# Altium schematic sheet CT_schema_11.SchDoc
size 632 x 434 mm
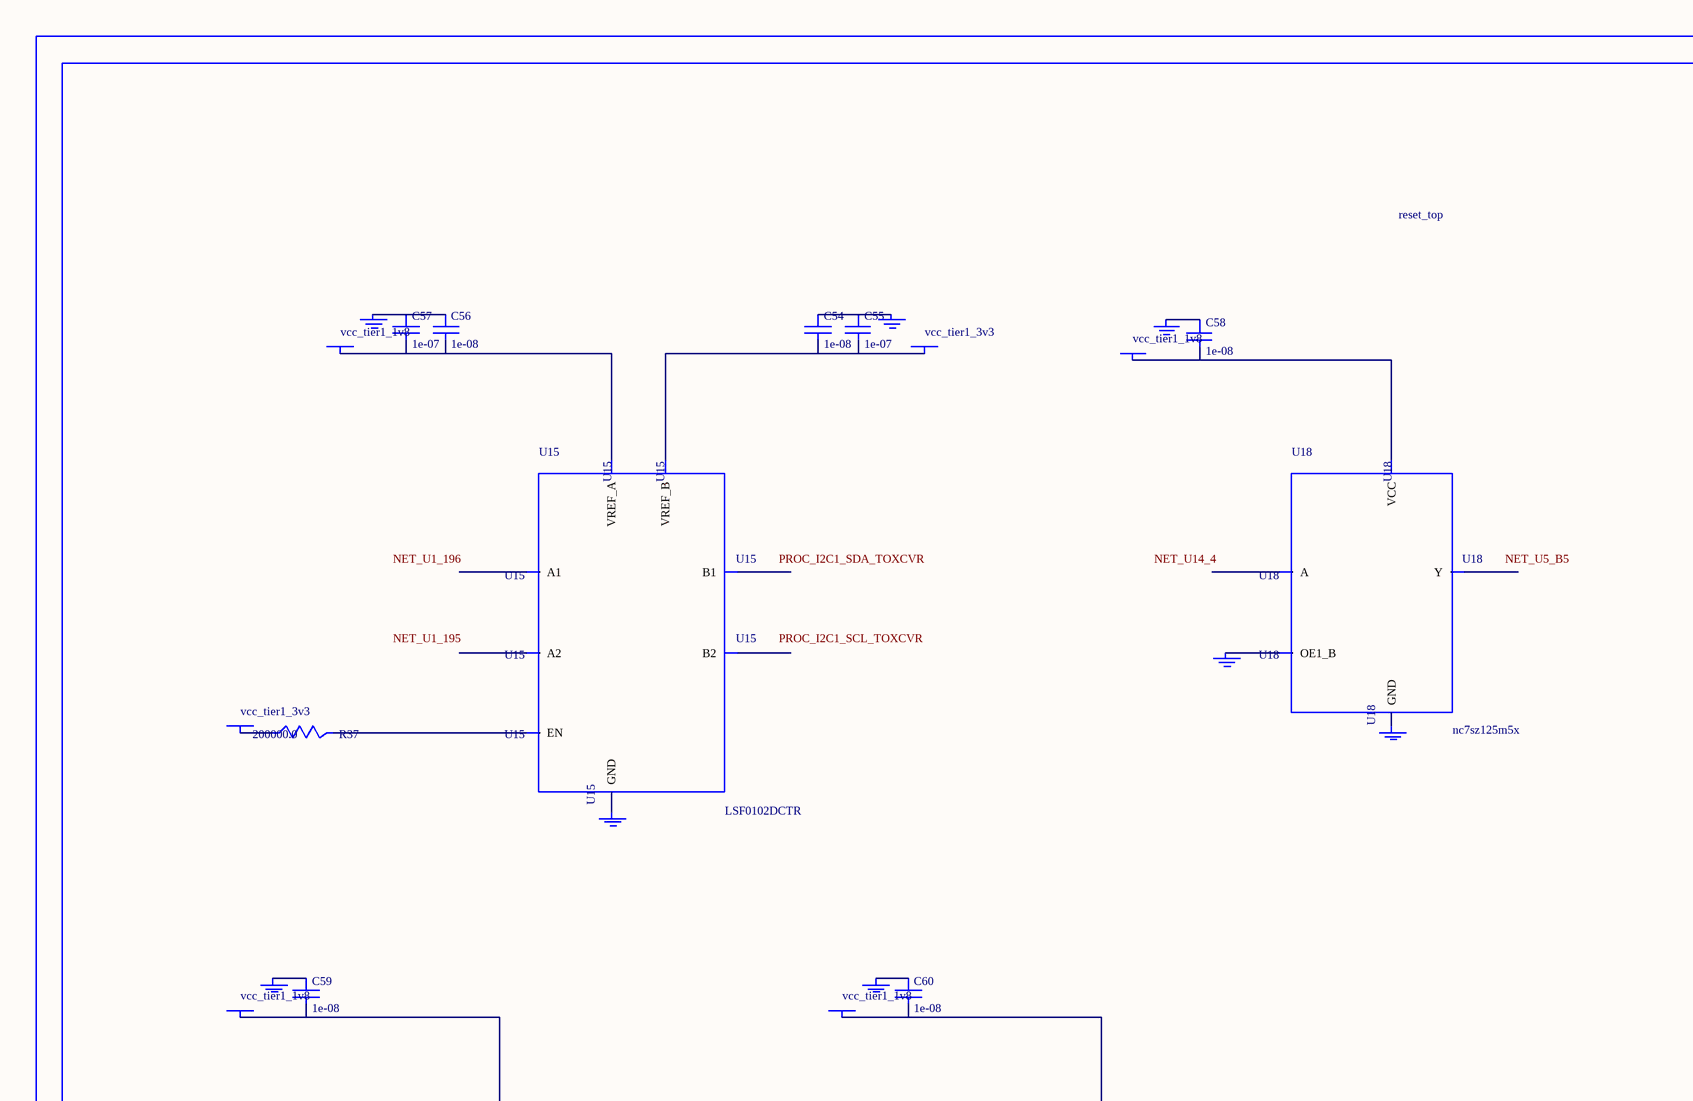
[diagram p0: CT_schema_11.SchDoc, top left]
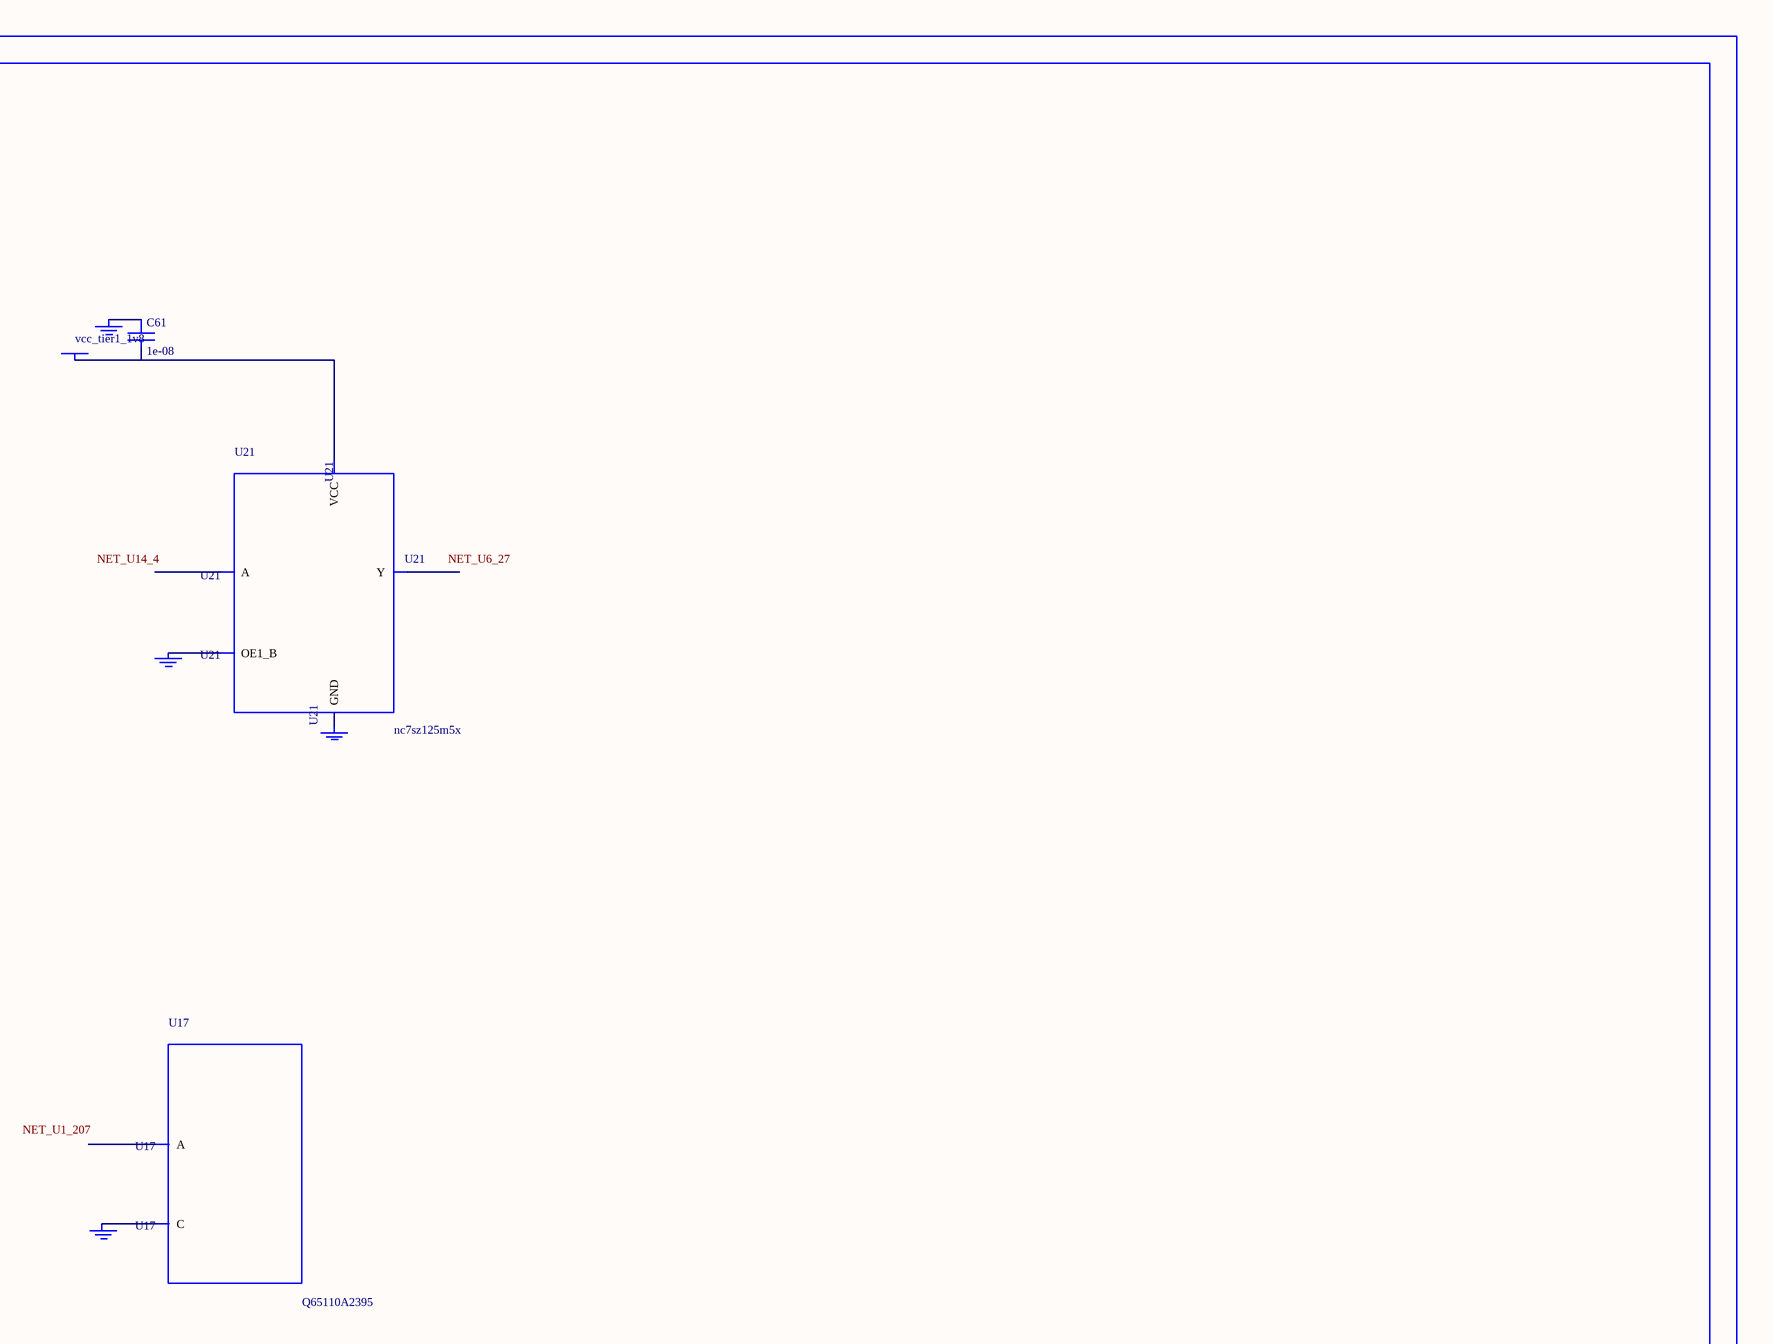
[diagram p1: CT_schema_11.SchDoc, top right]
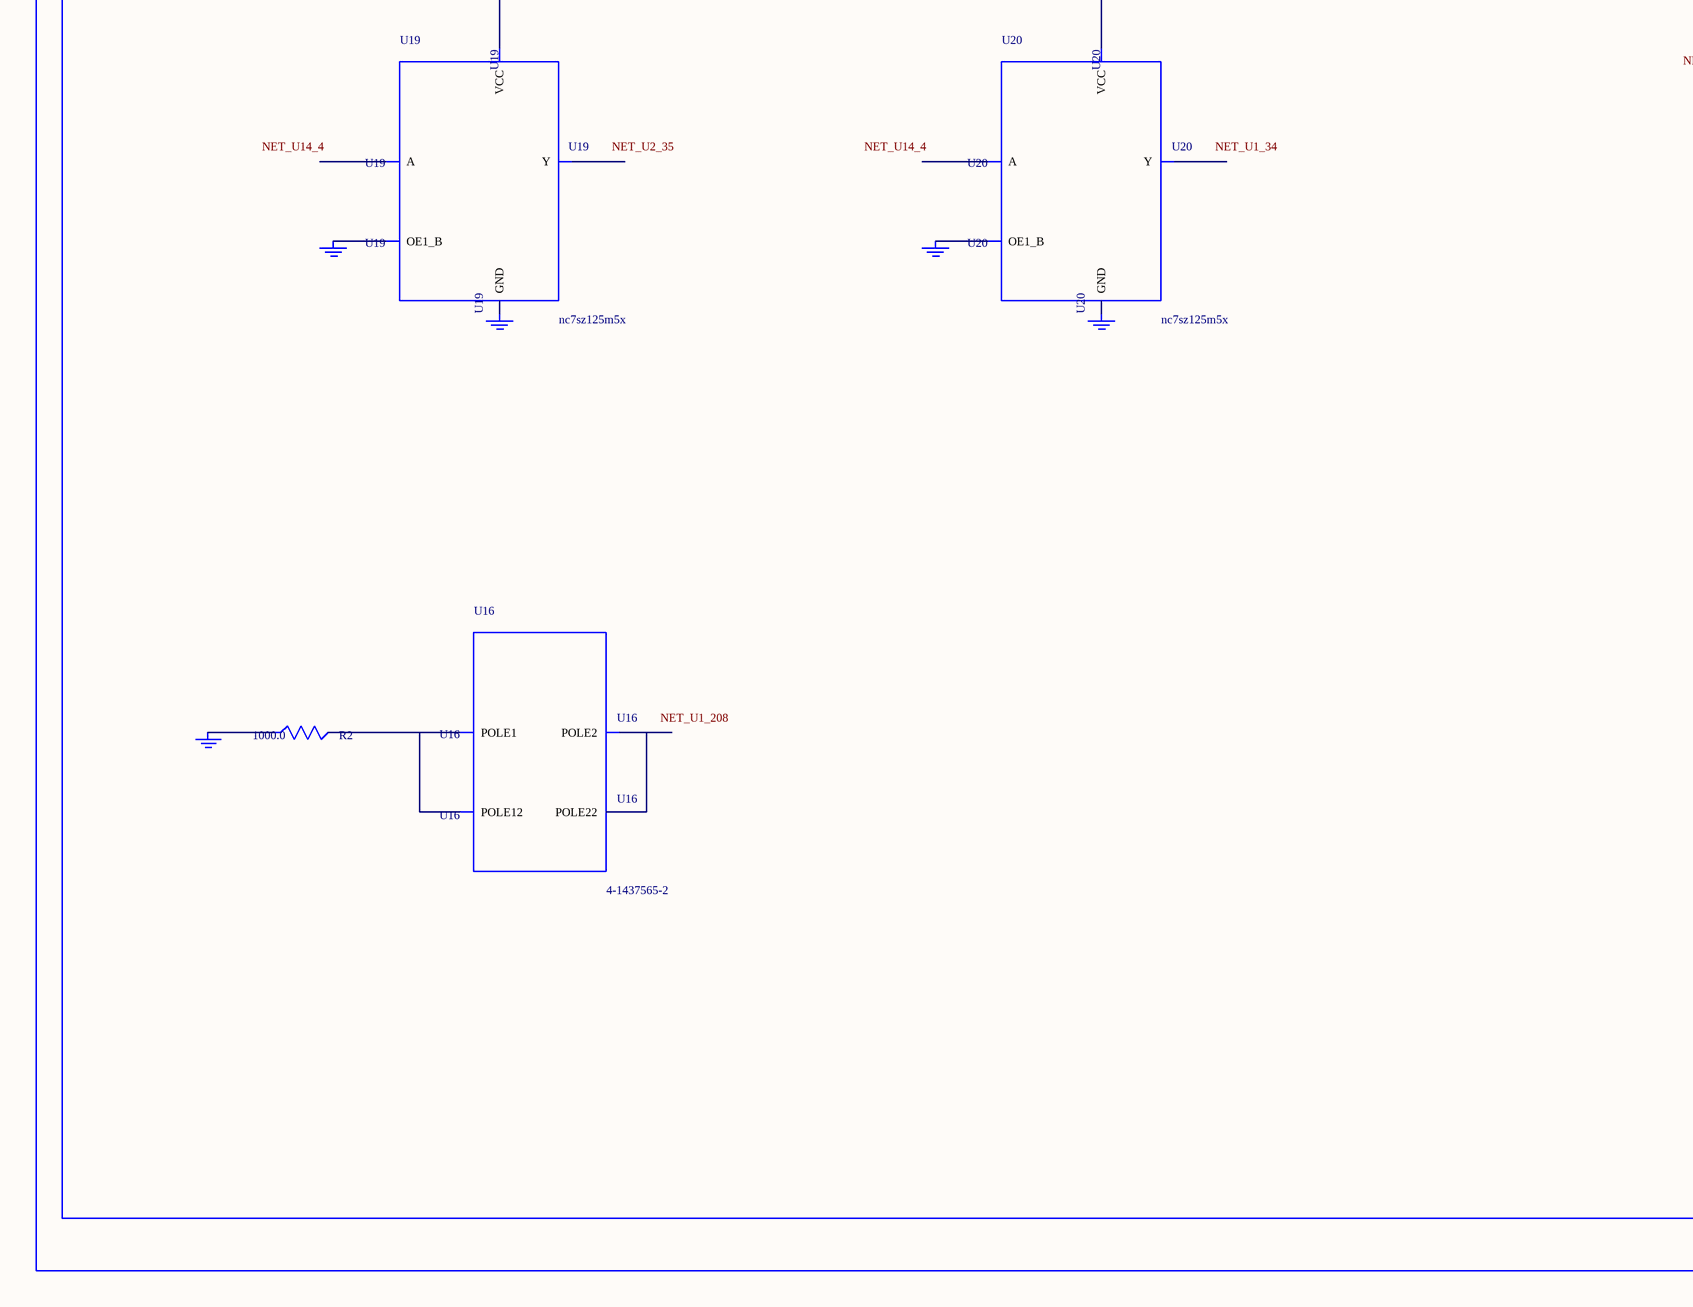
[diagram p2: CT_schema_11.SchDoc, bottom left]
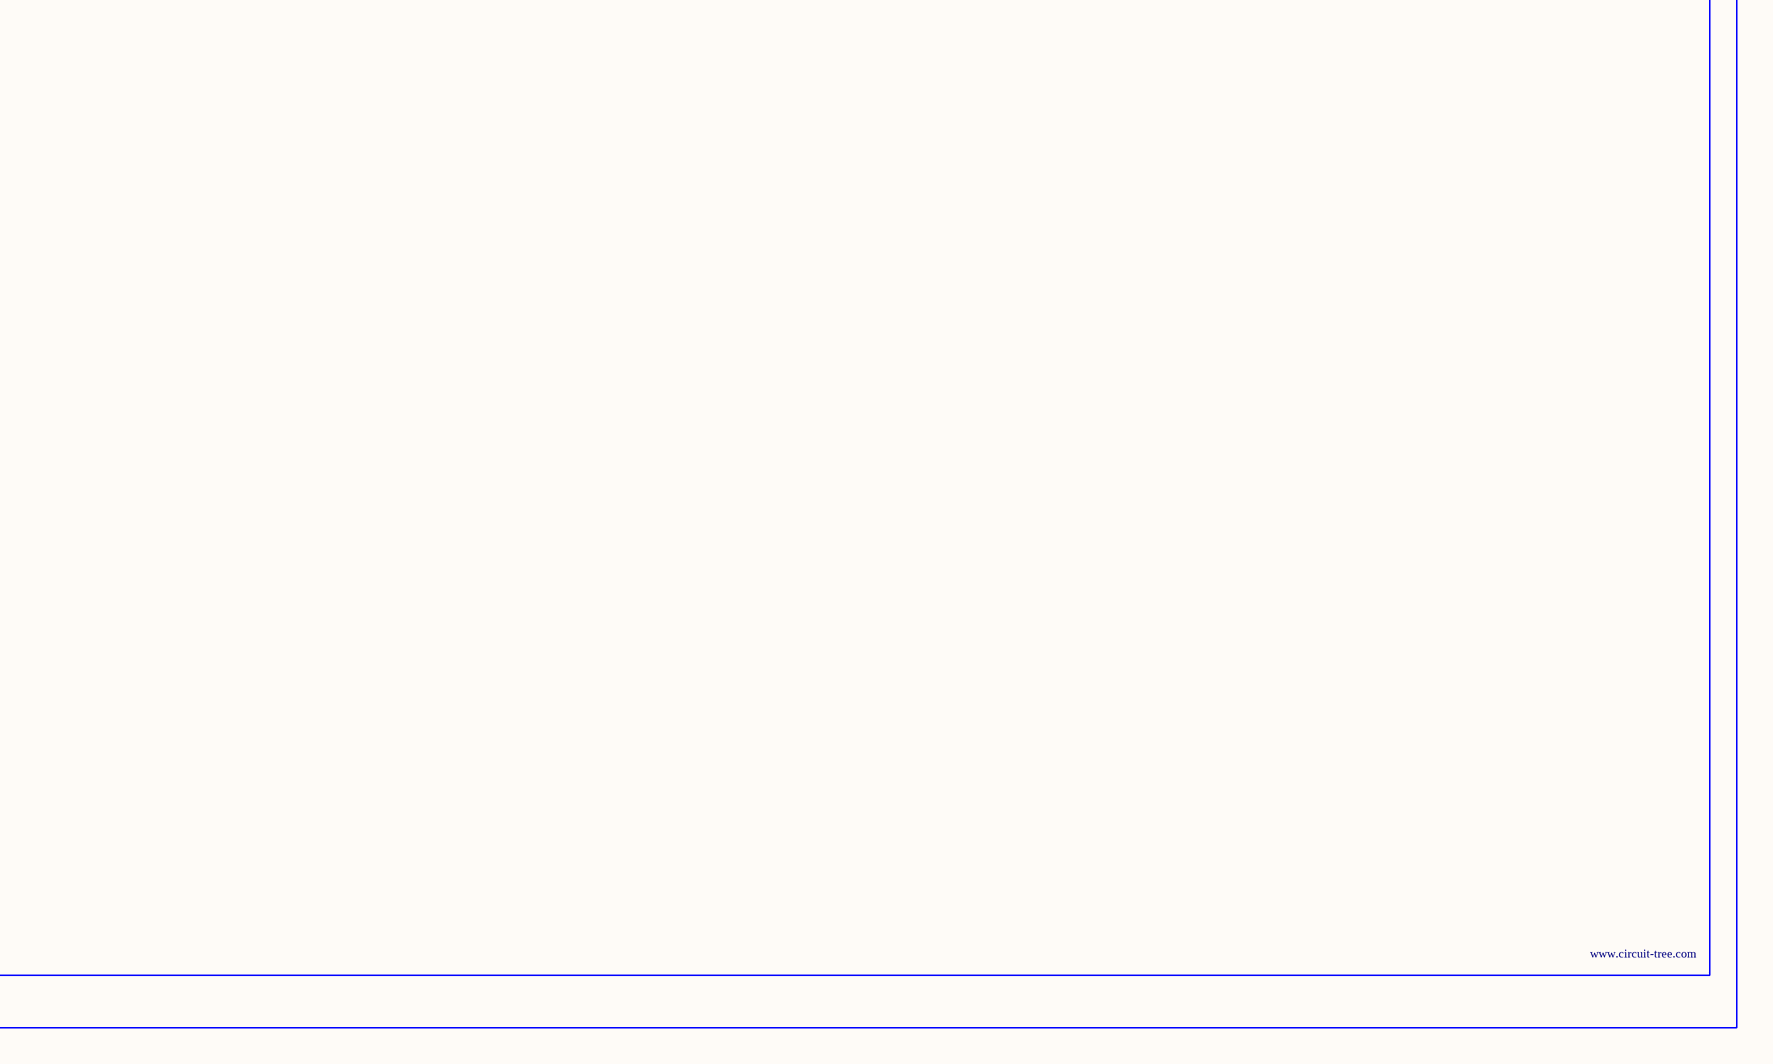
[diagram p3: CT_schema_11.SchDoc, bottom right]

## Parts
BORDER10  (no value)
C54  1e-08  [C0402]
C55  1e-07  [C0402]
C56  1e-08  [C0402]
C57  1e-07  [C0402]
C58  1e-08  [C0402]
C59  1e-08  [C0402]
C60  1e-08  [C0402]
C61  1e-08  [C0402]
GND_INSTANCE_10_0  (no value)
GND_INSTANCE_10_1  (no value)
GND_INSTANCE_10_2  (no value)
GND_INSTANCE_10_3  (no value)
GND_INSTANCE_10_4  (no value)
GND_INSTANCE_10_5  (no value)
GND_INSTANCE_10_6  (no value)
GND_INSTANCE_10_7  (no value)
GND_INSTANCE_10_8  (no value)
GND_INSTANCE_10_9  (no value)
GND_INSTANCE_10_10  (no value)
GND_INSTANCE_10_11  (no value)
GND_INSTANCE_10_12  (no value)
GND_INSTANCE_10_13  (no value)
GND_INSTANCE_10_14  (no value)
GND_INSTANCE_10_15  (no value)
GND_INSTANCE_10_16  (no value)
POWER_INSTANCE_10_0  vcc_tier1_1v8
POWER_INSTANCE_10_1  vcc_tier1_3v3
POWER_INSTANCE_10_2  vcc_tier1_3v3
POWER_INSTANCE_10_3  vcc_tier1_1v8
POWER_INSTANCE_10_4  vcc_tier1_1v8
POWER_INSTANCE_10_5  vcc_tier1_1v8
POWER_INSTANCE_10_6  vcc_tier1_1v8
R2  1000.0  [R0603]
R37  200000.0  [R0603]
U15  LSF0102DCTR  [DCU0008A_N]
U16  4-1437565-2  [SW_4-1437565-2]
U17  Q65110A2395  [LGM67K-G1J2-24-Z]
U18  nc7sz125m5x  [NC7SZ125M5X]
U19  nc7sz125m5x  [NC7SZ125M5X]
U20  nc7sz125m5x  [NC7SZ125M5X]
U21  nc7sz125m5x  [NC7SZ125M5X]

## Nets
NetC54_1: C54.1 C55.1 GND_INSTANCE_10_1.0(GND)
NetC54_2: C54.2 C55.2 POWER_INSTANCE_10_1.0(PWR) U15.7(VREF_B)
NetC56_1: C56.1 C57.1 GND_INSTANCE_10_0.0(GND)
NetC56_2: C56.2 C57.2 POWER_INSTANCE_10_0.0(PWR) U15.2(VREF_A)
NetC58_1: C58.1 GND_INSTANCE_10_5.0(GND)
NetC58_2: C58.2 POWER_INSTANCE_10_3.0(PWR) U18.5(VCC)
NetC59_1: C59.1 GND_INSTANCE_10_8.0(GND)
NetC59_2: C59.2 POWER_INSTANCE_10_4.0(PWR) U19.5(VCC)
NetC60_1: C60.1 GND_INSTANCE_10_11.0(GND)
NetC60_2: C60.2 POWER_INSTANCE_10_5.0(PWR) U20.5(VCC)
NetC61_1: C61.1 GND_INSTANCE_10_14.0(GND)
NetC61_2: C61.2 POWER_INSTANCE_10_6.0(PWR) U21.5(VCC)
NetGND_INSTANCE_10_2_0: GND_INSTANCE_10_2.0(GND) U15.1(GND)
NetGND_INSTANCE_10_3_0: GND_INSTANCE_10_3.0(GND) R2.1
NetGND_INSTANCE_10_4_0: GND_INSTANCE_10_4.0(GND) U17.C
NetGND_INSTANCE_10_6_0: GND_INSTANCE_10_6.0(GND) U18.1(OE1_B)
NetGND_INSTANCE_10_7_0: GND_INSTANCE_10_7.0(GND) U18.3(GND)
NetGND_INSTANCE_10_9_0: GND_INSTANCE_10_9.0(GND) U19.1(OE1_B)
NetGND_INSTANCE_10_10_0: GND_INSTANCE_10_10.0(GND) U19.3(GND)
NetGND_INSTANCE_10_12_0: GND_INSTANCE_10_12.0(GND) U20.1(OE1_B)
NetGND_INSTANCE_10_13_0: GND_INSTANCE_10_13.0(GND) U20.3(GND)
NetGND_INSTANCE_10_15_0: GND_INSTANCE_10_15.0(GND) U21.1(OE1_B)
NetGND_INSTANCE_10_16_0: GND_INSTANCE_10_16.0(GND) U21.3(GND)
NetPOWER_INSTANCE_10_2_0: POWER_INSTANCE_10_2.0(PWR) R37.1
NetR2_2: R2.2 U16.1(POLE1) U16.2(POLE12)
NetR37_2: R37.2 U15.8(EN)
NetU16_3: U16.3(POLE2) U16.4(POLE22)

Not connected (* = marked no-connect by the designer): U15 3(A1) 4(A2) 5(B2) 6(B1); U17 A; U18 2(A) 4(Y); U19 2(A) 4(Y); U20 2(A) 4(Y); U21 2(A) 4(Y)

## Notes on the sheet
- Labels drawn without touching a wire or pin: NET_U1_34, NET_U1_195, NET_U1_196, NET_U1_207, NET_U1_208, NET_U2_35, NET_U5_B5, NET_U6_27, NET_U14_4, PROC_I2C1_SCL_TOXCVR, PROC_I2C1_SDA_TOXCVR

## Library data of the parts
BORDER10 = BORDER_PAGE10
C54 C56 C58-C61 = C0402C103K3RAC
C55 C57 = C0402C104K3RACTU
GND_INSTANCE_10_0-GND_INSTANCE_10_16 = GND
POWER_INSTANCE_10_0-POWER_INSTANCE_10_6 = PWR
R2 = RC0603JR-071KL
R37 = RC0603JR-07200KL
